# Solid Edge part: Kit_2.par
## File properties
Sűrűség: 0,000 kg/m^3
Pontosság: 0,990
Author: ahadarics
Last saved by: psaghy
Revision: 78
Username: ahadarics
Dokumentum tartalom típus: 0
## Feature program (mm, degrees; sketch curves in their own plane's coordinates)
base feature "unnamed BaseFeature 1"
sketch for "Furat_1" plane through (0, 0, -190) normal (0, 0, -1) x-axis (1, 0, 0)
  hole centre (-110, 110) bore radius 8.647
hole "Furat_1" nominal diameter 20 finite  ThreadDepth = 25 mm
sketch for "unnamed Hole 1" plane through (0, 0, -190) normal (0, 0, -1) x-axis (1, 0, 0)
  hole centre (-110, -110) bore radius 8.647
hole "unnamed Hole 1" finite
sketch for "unnamed Hole 2" plane through (0, 0, -190) normal (0, 0, -1) x-axis (1, 0, 0)
  hole centre (110, -110) bore radius 8.647
hole "unnamed Hole 2" finite
sketch for "unnamed Hole 3" plane through (0, 0, -190) normal (0, 0, -1) x-axis (1, 0, 0)
  hole centre (110, 110) bore radius 8.647
hole "unnamed Hole 3" finite
pattern "unnamed Pattern 1" of "Furat_1", "unnamed Hole 1", "unnamed Hole 2", "unnamed Hole 3"
sketch for "Furat_5" plane through (25, -134, -160) normal (0, -1, 0) x-axis (0, 0, -1)
  hole centre (0, 0) bore radius 15.1455
hole "Furat_5" nominal diameter 33.249 finite  ThreadDepth = 20 mm
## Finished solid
Body 1: solid body, 528 faces, 1162 edges, 657 vertices, 2 internal voids.
  Faces by surface: cylinder 173, plane 114, torus 91, spline 90, cone 47, sphere 13
  Edges by curve: curve on surface 403, line 363, circle 342, spline 31, intersection 18, ellipse 5
Bounding box of the edges (mm; curved faces can reach further): 270.000 x 270.000 x 68.000, from (-135, -135, -198) to (135, 135, -130).
Cylindrical faces by radius (mm): R1 x12, R1.0011 x1, R3 x14, R3.0039 x1, R4 x35, R5 x1, R5.5 x1, R5.6 x1, R8 x40, R8.0046 x6, R8.0048 x6, R8.64 x4, R8.647 x4, R10 x8, R10.25 x4, R12 x1, R12.5 x1, R15.14 x1, R15.1455 x1, R16 x4, R20 x6, R22 x2, R24 x1, R26 x8, R30 x2, R45 x1, R47 x7
Conical faces (half-angle, radius in mm at the cone's reference point): 45 deg R5.35 x1, 45 deg R5.75 x1, 45 deg R7.9 x1, 45 deg R8.64 x12, 45 deg R10.4 x8, 45 deg R15.14 x1, 45 deg R15.75 x8, 45 deg R16.5 x4, 45 deg R18.5 x4, 45 deg R105.5858 x6, 59 deg R6.25 x1
Toroidal faces (ring radius, tube radius in mm): R2 r1 x1, R2 r8 x8, R7.0189 r3.0047 x6, R7.0189 r3.0048 x6, R7.0473 r3.0049 x8, R9 r8 x1, R11 r1 x8, R19 r1 x4, R23 r1 x2, R24 r4 x1, R25 r1 x4, R26 r4 x1, R28 r4 x1, R30 r4 x4, R34 r8 x8, R43 r2 x1, R46 r1 x2, R51 r4 x8, R55 r8 x5, R100.8431 r4 x6, R109.1569 r4 x6
Spherical faces by radius (mm): R4 x1, R4.0564 x12
Planar faces by outward normal: +x 7, +y 14, +z 5, -x 4, -y 21, -z 45, oblique 18
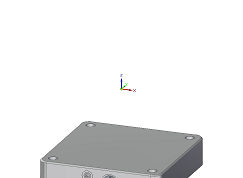
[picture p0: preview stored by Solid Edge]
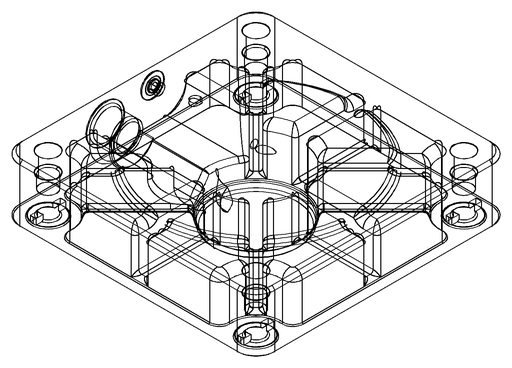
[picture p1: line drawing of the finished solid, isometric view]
